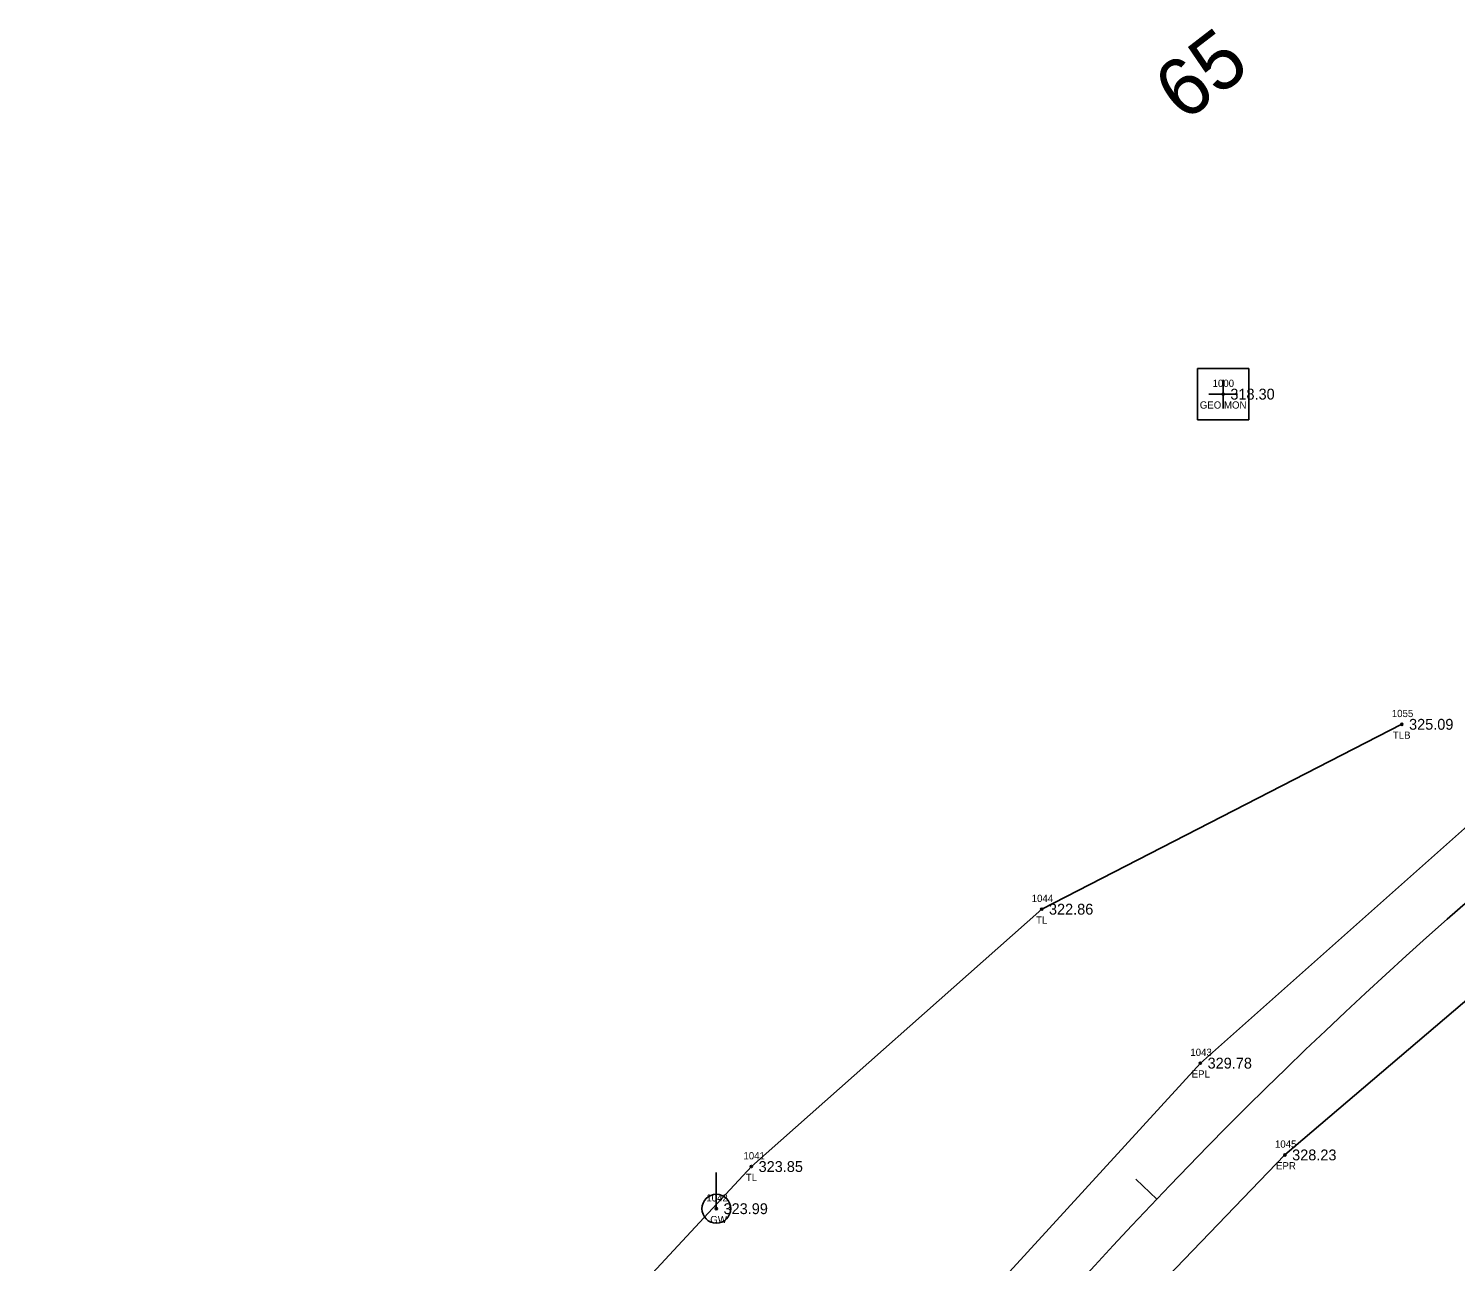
# Model space of a CAD drawing. Extents: x 2231119 to 2232595, y 1035731 to 1037094.
# Drawn here: x 2231253.8 to 2231451.3, y 1036309.5 to 1036480 of the extents above; entities that cross this region are included whole.
import ezdxf

# ---------------------------------------------------------------- set-up
doc = ezdxf.new("R2010")
doc.units = 0
for name, color, linetype in [('RD_EX_Road', 7, 'Continuous'), ('RD_EX_Road_txCode', 7, 'Continuous'), ('RD_EX_TX_Road_ELEV', 7, 'Continuous'), ('RD_EX_TX_UT_ELEV', 7, 'Continuous'), ('RD_EX_TX_VEG_ELEV', 7, 'Continuous'), ('RD_EX_UT', 7, 'Continuous'), ('RD_EX_UT_txCode', 7, 'Continuous'), ('RD_EX_VEG', 7, 'Continuous'), ('RD_EX_VEG_txCode', 7, 'Continuous'), ('RD_HC_Cl', 7, 'Continuous'), ('RD_HC_Data_Tic', 7, 'Continuous'), ('RD_HC_Survey', 7, 'Continuous'), ('RD_HC_Survey_ELEV', 7, 'Continuous'), ('RD_HC_TX_Sta50', 7, 'Continuous'), ('RD_SMD_Locator', 7, 'Continuous')]:
    doc.layers.add(name, color=color, linetype=linetype)

msp = doc.modelspace()

# ---------------------------------------------------------------- linework, layer by layer
at = {"layer": 'RD_EX_Road'}
for points in [[(2231158.42, 1035748.11), (2231188.37, 1035851.38), (2231216.59, 1035946.92), (2231244.77, 1036040.72), (2231278.59, 1036133.31), (2231299.55, 1036179.73), (2231323.11, 1036221.2), (2231350.7, 1036262.3), (2231381.59, 1036299.29), (2231415.97, 1036336.9), (2231452.94, 1036369.74), (2231498.19, 1036405.3), (2231537.2, 1036432.57), (2231541.46, 1036424.96)], [(2231176.43, 1035742.89), (2231206.61, 1035845.83), (2231234.19, 1035940.65), (2231261.92, 1036033.75), (2231294.68, 1036125.28), (2231316.11, 1036171.75), (2231338.19, 1036211.09), (2231363.83, 1036252.38), (2231394.08, 1036289.28), (2231427.67, 1036324.2), (2231464.37, 1036355.5), (2231508.96, 1036392.41), (2231546.55, 1036416.22), (2231541.46, 1036424.96)]]:
    msp.add_lwpolyline(points, dxfattribs=at)
at = {"layer": 'RD_EX_UT'}
msp.add_line((2231348.99, 1036316.76), (2231348.99, 1036321.76), dxfattribs=at)
msp.add_circle((2231348.99, 1036316.76), 2, dxfattribs=at)
at = {"layer": 'RD_EX_VEG'}
msp.add_lwpolyline([(2231141.61, 1035753.39), (2231172.54, 1035856.04), (2231200.09, 1035950.41), (2231226.19, 1036046.04), (2231262.9, 1036139.62), (2231281.03, 1036187.82), (2231303.66, 1036232.51), (2231318.61, 1036284.65), (2231353.84, 1036322.59), (2231394.02, 1036358.2), (2231443.85, 1036383.78)], dxfattribs=at)
at = {"layer": 'RD_HC_Cl'}
msp.add_arc((2231880.38, 1035870.33), 649.46, 120.68197, 163.7355, dxfattribs=at)
at = {"layer": 'RD_HC_Data_Tic'}
msp.add_line((2231409.93, 1036318.07), (2231407.03, 1036320.83), dxfattribs=at)
at = {"layer": 'RD_HC_Survey'}
for p, q in [((2231419.12, 1036427.46), (2231419.12, 1036431.46)), ((2231421.12, 1036429.46), (2231417.12, 1036429.46))]:
    msp.add_line(p, q, dxfattribs=at)
msp.add_lwpolyline([(2231422.66, 1036432.99), (2231415.59, 1036432.99), (2231415.59, 1036425.92), (2231422.66, 1036425.92)], close=True, dxfattribs=at)
at = {"layer": 'RD_SMD_Locator'}
for centre in [(2231419.12, 1036429.46), (2231443.85, 1036383.78), (2231394.02, 1036358.2), (2231415.97, 1036336.9), (2231427.67, 1036324.2), (2231353.84, 1036322.59), (2231348.99, 1036316.76)]:
    msp.add_circle(centre, 0.15, dxfattribs=at)

# ---------------------------------------------------------------- texts
at = {"layer": 'RD_EX_Road_txCode'}
for s, p in [('1043', (2231414.58, 1036337.9)), ('EPL', (2231414.76, 1036334.9)), ('1045', (2231426.29, 1036325.2)), ('EPR', (2231426.44, 1036322.2))]:
    msp.add_text(s, height=1, dxfattribs=at).set_placement(p)
at = {"layer": 'RD_EX_TX_Road_ELEV'}
for s, p in [('329.78', (2231416.97, 1036336.15)), ('328.23', (2231428.67, 1036323.45))]:
    msp.add_text(s, height=1.5, dxfattribs=at).set_placement(p)
at = {"layer": 'RD_EX_TX_UT_ELEV'}
msp.add_text('323.99', height=1.5, dxfattribs=at).set_placement((2231349.99, 1036316.01))
at = {"layer": 'RD_EX_TX_VEG_ELEV'}
for s, p in [('325.09', (2231444.85, 1036383.03)), ('322.86', (2231395.02, 1036357.45)), ('323.85', (2231354.84, 1036321.84))]:
    msp.add_text(s, height=1.5, dxfattribs=at).set_placement(p)
at = {"layer": 'RD_EX_UT_txCode'}
for s, p in [('1042', (2231347.6, 1036317.76)), ('GW', (2231348.15, 1036314.76))]:
    msp.add_text(s, height=1, dxfattribs=at).set_placement(p)
at = {"layer": 'RD_EX_VEG_txCode'}
for s, p in [('1055', (2231442.46, 1036384.78)), ('TLB', (2231442.6, 1036381.78)), ('1044', (2231392.63, 1036359.2)), ('TL', (2231393.24, 1036356.2)), ('1041', (2231352.74, 1036323.59)), ('TL', (2231353.07, 1036320.59))]:
    msp.add_text(s, height=1, dxfattribs=at).set_placement(p)
at = {"layer": 'RD_HC_Survey'}
for s, p in [('1000', (2231417.66, 1036430.46)), ('GEO MON', (2231415.89, 1036427.46))]:
    msp.add_text(s, height=1, dxfattribs=at).set_placement(p)
at = {"layer": 'RD_HC_Survey_ELEV'}
msp.add_text('318.30', height=1.5, dxfattribs=at).set_placement((2231420.12, 1036428.71))
at = {"layer": 'RD_HC_TX_Sta50'}
msp.add_text('65', height=8, rotation=37.5948, dxfattribs=at).set_placement((2231413.71, 1036466.98))

doc.saveas('drawing.dxf')
